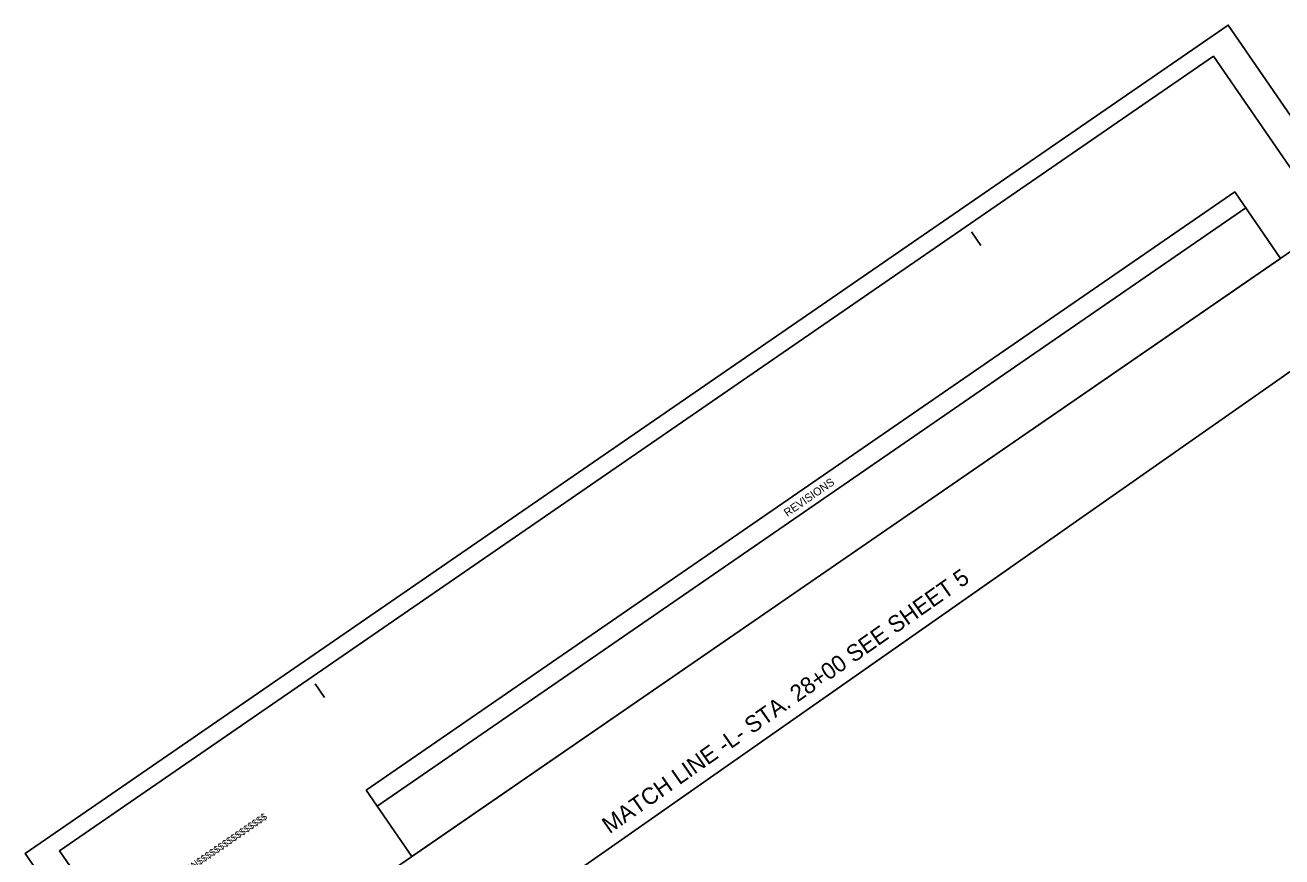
# Model space of a CAD drawing. Extents: x 2297526 to 2298642, y 599613 to 600819.
# Drawn here: x 2297526 to 2298094, y 600444 to 600819 of the extents above; entities that cross this region are included whole.
import ezdxf

# ---------------------------------------------------------------- set-up
doc = ezdxf.new("R2010")
doc.units = 0
for name, color, linetype in [('COGO Default Point Elevation', 7, 'Continuous'), ('COGO Default Point Number', 7, 'Continuous'), ('Exist DTM Drainline Cogo Comment', 7, 'Continuous'), ('Exist DTM Drainline Cogo Elevation', 7, 'Continuous'), ('Exist Property Iron Pin Cogo Number', 7, 'Continuous'), ('Exist Roads Curbs Cogo Number', 7, 'Continuous'), ('Exist Roads Curbs Cogo Point CELL', 7, 'Continuous'), ('Exist Roads EOP Other Cogo Comment', 7, 'Continuous')]:
    doc.layers.add(name, color=color, linetype=linetype)

msp = doc.modelspace()

# ---------------------------------------------------------------- linework, layer by layer
at = {"layer": 'COGO Default Point Elevation'}
msp.add_line((2297786.19, 600444.87), (2297970.49, 600573.93), dxfattribs=at)
at = {"layer": 'Exist DTM Drainline Cogo Comment'}
msp.add_lwpolyline([(2298629.8, 599981.76), (2298062.67, 600805.27), (2297541.29, 600446.21), (2298108.42, 599622.7)], close=True, dxfattribs=at)
at = {"layer": 'Exist DTM Drainline Cogo Elevation'}
for p, q in [((2297953.33, 600725.96), (2297957.59, 600719.79)), ((2297656.84, 600521.78), (2297661.1, 600515.6))]:
    msp.add_line(p, q, dxfattribs=at)
msp.add_lwpolyline([(2298624.28, 599987.07), (2298113.82, 600728.3), (2297594.96, 600370.97), (2298105.42, 599629.74)], close=True, dxfattribs=at)
at = {"layer": 'Exist Property Iron Pin Cogo Number'}
msp.add_lwpolyline([(2297647.43, 600347.7), (2298036.32, 599783), (2298066.14, 599803.53), (2298144.6, 599689.59), (2298480.39, 599975.84), (2298444.85, 600027.45), (2298522.99, 600081.26), (2298287.23, 600423.6), (2298114.33, 600674.66)], close=True, dxfattribs=at)
at = {"layer": 'Exist Roads Curbs Cogo Number'}
msp.add_lwpolyline([(2298113.82, 600728.3), (2297594.98, 600370.97), (2298105.44, 599629.74), (2298525.54, 599919.07), (2298457.47, 600017.93), (2298556.21, 600085.92)], close=True, dxfattribs=at)
at = {"layer": 'Exist Roads Curbs Cogo Point CELL'}
msp.add_lwpolyline([(2298642.42, 599987.17), (2298069.34, 600819.33), (2297525.77, 600444.99), (2298098.85, 599612.83)], close=True, dxfattribs=at)
at = {"layer": 'Exist Roads EOP Other Cogo Comment'}
msp.add_line((2297684.79, 600466.49), (2298077.26, 600736.79), dxfattribs=at)
msp.add_lwpolyline([(2297679.8, 600473.71), (2298072.29, 600744), (2298092.99, 600713.96), (2297700.51, 600443.66)], close=True, dxfattribs=at)

# ---------------------------------------------------------------- texts
at = {"layer": 'COGO Default Point Number'}
msp.add_text('MATCH LINE -L- STA. 28+00 SEE SHEET 5', height=7.5, rotation=35.0027, dxfattribs=at).set_placement((2297789.81, 600453.75))
at = {"layer": 'Exist DTM Drainline Cogo Elevation'}
msp.add_text('$$$$$$$$$$$$$$$$DGN$$$$$$$$$$$$$$$$', height=3.15, rotation=34.5541, dxfattribs=at).set_placement((2297565.95, 600413.09))
at = {"layer": 'Exist Roads EOP Other Cogo Comment'}
msp.add_text('REVISIONS', height=3.616, rotation=34.5541, dxfattribs=at).set_placement((2297870.13, 600597.09))

doc.saveas('drawing.dxf')
